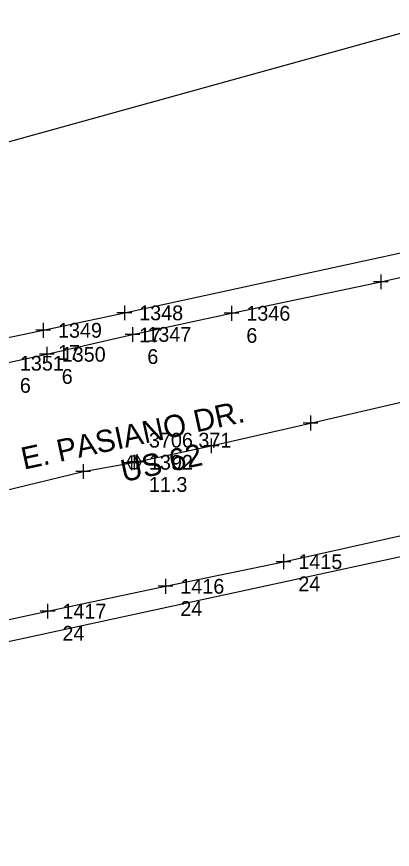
# Model space of a CAD drawing. Extents: x 352921 to 392463, y 10654752 to 10749237.
# Drawn here: x 389283 to 389410, y 10658730.9 to 10659012.6 of the extents above; entities that cross this region are included whole.
import ezdxf

# ---------------------------------------------------------------- set-up
doc = ezdxf.new("R2010")
doc.units = 0
for name, color, linetype in [('GAS', 7, 'Continuous'), ('GAS_#', 7, 'Continuous'), ('GAS_DES', 7, 'Continuous'), ('GAS_SPOT', 7, 'Continuous'), ('LIMITS', 7, 'Continuous'), ('ROAD NAMES', 7, 'Continuous'), ('TC', 7, 'Continuous'), ('TC_#', 7, 'Continuous'), ('TC_DES', 7, 'Continuous'), ('TC_ELEV', 7, 'Continuous'), ('TC_SPOT', 7, 'Continuous'), ('UE', 7, 'Continuous'), ('UE_#', 7, 'Continuous'), ('UE_DES', 7, 'Continuous'), ('UE_ELEV', 7, 'Continuous'), ('UE_SPOT', 7, 'Continuous'), ('W_#', 7, 'Continuous'), ('W_DES', 7, 'Continuous'), ('W_SPOT', 7, 'Continuous'), ('WATER', 7, 'Continuous')]:
    doc.layers.add(name, color=color, linetype=linetype)

msp = doc.modelspace()

# ---------------------------------------------------------------- linework, layer by layer
at = {"layer": 'GAS'}
msp.add_lwpolyline([(389072.6, 10658760.4), (389078.62, 10658763.36), (389090.08, 10658766.74), (389198.96, 10658790.73), (389231.32, 10658798.04), (389293.44, 10658811.44), (389333.32, 10658819.87), (389373.23, 10658828.19), (389417.63, 10658838.09), (389441.59, 10658843.51), (389468.71, 10658849.13), (389508.62, 10658858.22), (389630.93, 10658885.56), (389658.83, 10658891.85)], dxfattribs=at)
at = {"layer": 'GAS_SPOT'}
for p, q in [((389373.23, 10658830.69), (389373.23, 10658825.69)), ((389375.73, 10658828.19), (389370.73, 10658828.19)), ((389333.32, 10658822.37), (389333.32, 10658817.37)), ((389335.82, 10658819.87), (389330.82, 10658819.87)), ((389293.44, 10658813.94), (389293.44, 10658808.94)), ((389295.94, 10658811.44), (389290.94, 10658811.44))]:
    msp.add_line(p, q, dxfattribs=at)
at = {"layer": 'LIMITS'}
for p, q in [((389093.88, 10658918.64), (389688.35, 10659083.49)), ((388080.78, 10658541.98), (390234.87, 10659007.56))]:
    msp.add_line(p, q, dxfattribs=at)
at = {"layer": 'TC'}
msp.add_lwpolyline([(389183.93, 10658879.2), (389197.16, 10658882), (389196.9, 10658874.62), (389190.7, 10658854.36), (389188.21, 10658837.81), (389188.11, 10658831.21), (389188.71, 10658830.92), (389206.05, 10658835.56), (389236.83, 10658842.99), (389278.53, 10658852.15), (389305.48, 10658858.72), (389321.86, 10658861.65), (389323.61, 10658862.04), (389348.79, 10658867.39), (389382.38, 10658875.13), (389415.42, 10658882.74)], dxfattribs=at)
msp.add_lwpolyline([(389325.1, 10658861.83), (389323.9, 10658863.91), (389321.5, 10658863.91), (389320.3, 10658861.83), (389321.5, 10658859.76), (389323.9, 10658859.76)], close=True, dxfattribs=at)
msp.add_lwpolyline([(389325.1, 10658861.83), (389323.9, 10658863.91), (389321.5, 10658863.91), (389320.3, 10658861.83), (389321.5, 10658859.76), (389323.9, 10658859.76)], close=True, dxfattribs=at)
at = {"layer": 'TC_SPOT'}
for p, q in [((389325.2, 10658861.83), (389320.2, 10658861.83)), ((389322.7, 10658864.33), (389322.7, 10658859.33))]:
    msp.add_line(p, q, dxfattribs=at)
at = {"layer": 'UE'}
msp.add_lwpolyline([(389165.95, 10658878.91), (389182.2, 10658879.46), (389196.15, 10658882.77), (389207.11, 10658884.3), (389215.93, 10658884.01), (389252.81, 10658889.65), (389253.73, 10658889.17), (389254.19, 10658889.7), (389259.9, 10658891.43), (389279.05, 10658895.36), (389293.2, 10658898.38), (389322.16, 10658905.11), (389355.65, 10658912.26), (389406.1, 10658922.87), (389436.51, 10658929.81)], dxfattribs=at)
at = {"layer": 'UE_SPOT'}
for p, q in [((389406.1, 10658925.37), (389406.1, 10658920.37)), ((389408.6, 10658922.87), (389403.6, 10658922.87)), ((389355.65, 10658914.76), (389355.65, 10658909.76)), ((389358.15, 10658912.26), (389353.15, 10658912.26)), ((389322.16, 10658907.61), (389322.16, 10658902.61)), ((389324.66, 10658905.11), (389319.66, 10658905.11)), ((389295.7, 10658898.38), (389290.7, 10658898.38)), ((389293.2, 10658900.88), (389293.2, 10658895.88)), ((389382.38, 10658877.63), (389382.38, 10658872.63)), ((389384.88, 10658875.13), (389379.88, 10658875.13)), ((389351.29, 10658867.39), (389346.29, 10658867.39)), ((389348.79, 10658869.89), (389348.79, 10658864.89)), ((389323.61, 10658864.54), (389323.61, 10658859.54)), ((389324.36, 10658861.65), (389319.36, 10658861.65)), ((389326.11, 10658862.04), (389321.11, 10658862.04)), ((389321.86, 10658864.15), (389321.86, 10658859.15)), ((389305.48, 10658861.22), (389305.48, 10658856.22)), ((389307.98, 10658858.72), (389302.98, 10658858.72))]:
    msp.add_line(p, q, dxfattribs=at)
at = {"layer": 'W_SPOT'}
for p, q in [((389321.9, 10658912.41), (389316.9, 10658912.41)), ((389319.4, 10658914.91), (389319.4, 10658909.91)), ((389291.95, 10658909), (389291.95, 10658904)), ((389294.45, 10658906.5), (389289.45, 10658906.5))]:
    msp.add_line(p, q, dxfattribs=at)
at = {"layer": 'WATER'}
msp.add_lwpolyline([(389188.12, 10658884.4), (389192.7, 10658885.15), (389215.6, 10658889.8), (389215.69, 10658889.79), (389257.15, 10658899.16), (389291.95, 10658906.5), (389319.4, 10658912.41), (389460.58, 10658943.13)], dxfattribs=at)

# ---------------------------------------------------------------- texts
at = {"layer": 'GAS_#'}
for s, p in [('1415', (389378.23, 10658825.69)), ('1416', (389338.32, 10658817.37)), ('1417', (389298.44, 10658808.94))]:
    msp.add_text(s, height=5, dxfattribs=at).set_placement(p)
at = {"layer": 'GAS_DES'}
for p in [(389378.23, 10658818.19), (389338.32, 10658809.87), (389298.44, 10658801.44)]:
    msp.add_text('24', height=5, dxfattribs=at).set_placement(p)
at = {"layer": 'ROAD NAMES'}
for s, p in [('E. PASIANO DR.', (389285.41, 10658859.32)), ('US 62', (389319.07, 10658855.08))]:
    msp.add_text(s, height=7.5, rotation=12.1964, dxfattribs=at).set_placement(p)
at = {"layer": 'TC_#'}
msp.add_text('1392', height=5, dxfattribs=at).set_placement((389327.7, 10658859.33))
at = {"layer": 'TC_DES'}
msp.add_text('11.3', height=5, dxfattribs=at).set_placement((389327.7, 10658851.83))
at = {"layer": 'TC_ELEV'}
msp.add_text('3706.371', height=5, dxfattribs=at).set_placement((389327.7, 10658866.83))
at = {"layer": 'UE_#'}
for s, height, p in [('1346', 5, (389360.65, 10658909.76)), ('1347', 5, (389327.16, 10658902.61)), ('1350', 5, (389298.2, 10658895.88)), ('1351', 5, (389284.05, 10658892.86)), ('1389', 0.15, (389382.53, 10658875.05)), ('1390', 0.15, (389348.94, 10658867.32)), ('1393', 0.15, (389322.01, 10658861.57)), ('1391', 0.15, (389323.76, 10658861.96)), ('1394', 0.15, (389305.63, 10658858.64))]:
    msp.add_text(s, height=height, dxfattribs=at).set_placement(p)
at = {"layer": 'UE_DES'}
for s, height, p in [('6', 5, (389360.65, 10658902.26)), ('6', 5, (389327.16, 10658895.11)), ('6', 5, (389298.2, 10658888.38)), ('6', 5, (389284.05, 10658885.36)), ('13', 0.15, (389382.53, 10658874.83)), ('13', 0.15, (389348.94, 10658867.09)), ('13', 0.15, (389323.76, 10658861.74)), ('13', 0.15, (389322.01, 10658861.35)), ('13', 0.15, (389305.63, 10658858.42))]:
    msp.add_text(s, height=height, dxfattribs=at).set_placement(p)
at = {"layer": 'UE_ELEV'}
for s, p in [('3706.310', (389382.53, 10658875.28)), ('3706.332', (389348.94, 10658867.54)), ('3706.409', (389322.01, 10658861.8)), ('3706.365', (389323.76, 10658862.19)), ('3706.322', (389305.63, 10658858.87))]:
    msp.add_text(s, height=0.15, dxfattribs=at).set_placement(p)
at = {"layer": 'W_#'}
for s, p in [('1348', (389324.4, 10658909.91)), ('1349', (389296.95, 10658904))]:
    msp.add_text(s, height=5, dxfattribs=at).set_placement(p)
at = {"layer": 'W_DES'}
for p in [(389324.4, 10658902.41), (389296.95, 10658896.5)]:
    msp.add_text('17', height=5, dxfattribs=at).set_placement(p)

doc.saveas('drawing.dxf')
